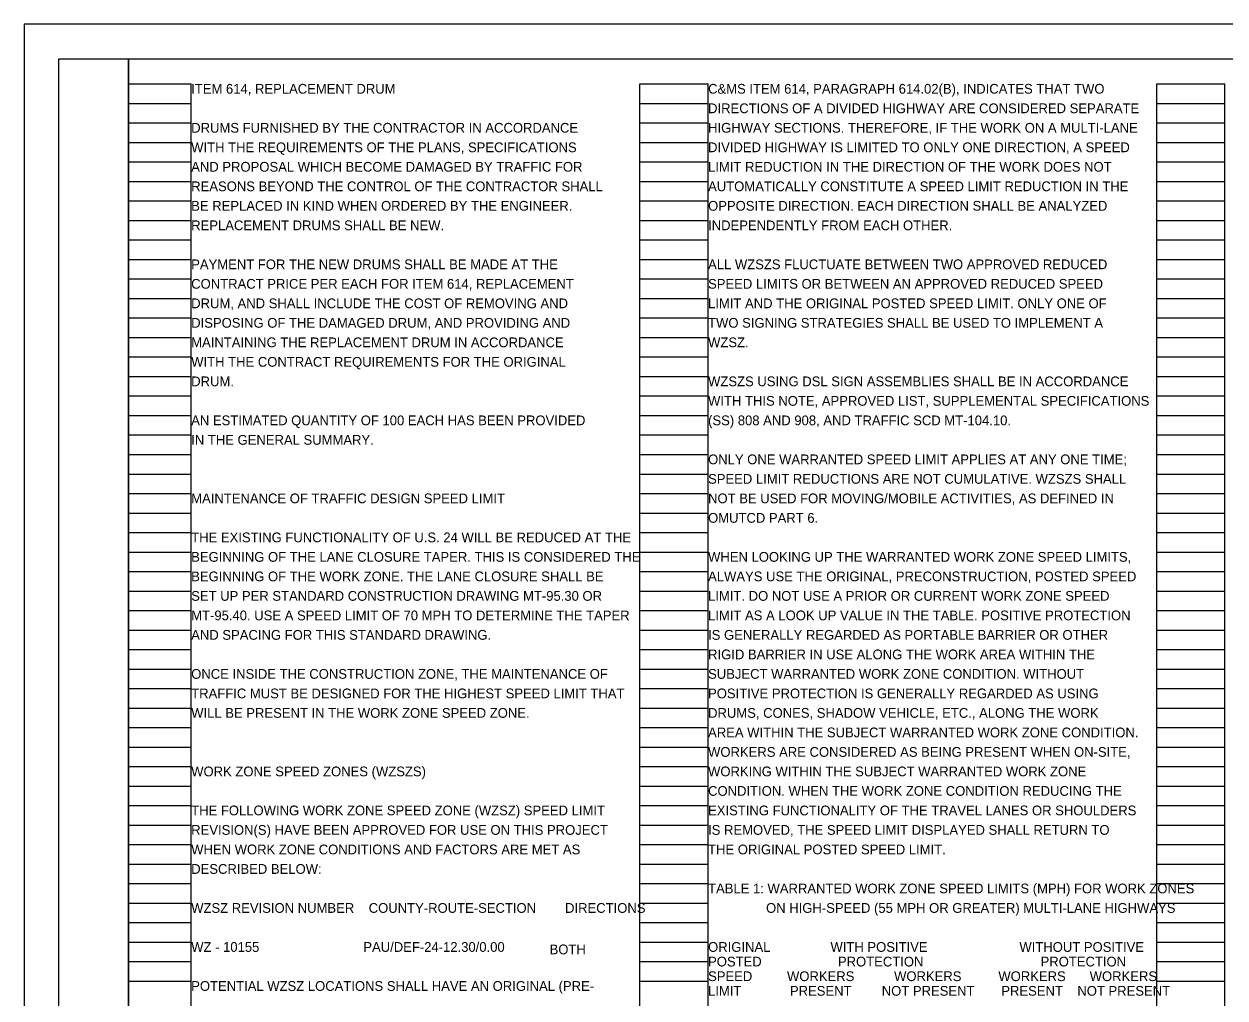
# Model space of a CAD drawing. Extents: x 0 to 34, y -6.1 to 22.
# Drawn here: x 0 to 17.24, y 8.02 to 22 of the extents above; entities that cross this region are included whole.
import ezdxf

# ---------------------------------------------------------------- set-up
doc = ezdxf.new("R2010")
doc.units = 0
for name, color, linetype in [('SH_Border', 7, 'Continuous'), ('SH_Cut_Line', 7, 'Continuous'), ('SH_Data', 7, 'Continuous'), ('SH_Text', 7, 'Continuous')]:
    doc.layers.add(name, color=color, linetype=linetype)

msp = doc.modelspace()

# ---------------------------------------------------------------- linework, layer by layer
at = {"layer": 'SH_Border'}
for points in [[(0.5, 21.5), (1.5, 21.5), (1.5, 0.5), (0.5, 0.5)], [(1.5, 21.5), (33.5, 21.5), (33.5, 0.5), (1.5, 0.5)]]:
    msp.add_lwpolyline(points, close=True, dxfattribs=at)
at = {"layer": 'SH_Cut_Line'}
msp.add_lwpolyline([(0, 0), (34, 0), (34, 22), (0, 22)], close=True, dxfattribs=at)
at = {"layer": 'SH_Data'}
for p, q in [((1.5, 0.98), (1.5, 21.14)), ((1.5, 21.14), (2.4, 21.14)), ((2.4, 0.98), (2.4, 21.14)), ((8.84, 0.98), (8.84, 21.14)), ((8.84, 21.14), (9.82, 21.14)), ((9.82, 0.98), (9.82, 21.14)), ((16.26, 0.98), (16.26, 21.14)), ((16.26, 21.14), (17.24, 21.14)), ((17.24, 0.98), (17.24, 21.14)), ((1.5, 20.86), (2.4, 20.86)), ((8.84, 20.86), (9.82, 20.86)), ((16.26, 20.86), (17.24, 20.86)), ((1.5, 20.58), (2.4, 20.58)), ((8.84, 20.58), (9.82, 20.58)), ((16.26, 20.58), (17.24, 20.58)), ((1.5, 20.3), (2.4, 20.3)), ((8.84, 20.3), (9.82, 20.3)), ((16.26, 20.3), (17.24, 20.3)), ((1.5, 20.02), (2.4, 20.02)), ((8.84, 20.02), (9.82, 20.02)), ((16.26, 20.02), (17.24, 20.02)), ((1.5, 19.74), (2.4, 19.74)), ((8.84, 19.74), (9.82, 19.74)), ((16.26, 19.74), (17.24, 19.74)), ((1.5, 19.46), (2.4, 19.46)), ((8.84, 19.46), (9.82, 19.46)), ((16.26, 19.46), (17.24, 19.46)), ((1.5, 19.18), (2.4, 19.18)), ((8.84, 19.18), (9.82, 19.18)), ((16.26, 19.18), (17.24, 19.18)), ((1.5, 18.9), (2.4, 18.9)), ((8.84, 18.9), (9.82, 18.9)), ((16.26, 18.9), (17.24, 18.9)), ((1.5, 18.62), (2.4, 18.62)), ((8.84, 18.62), (9.82, 18.62)), ((16.26, 18.62), (17.24, 18.62)), ((1.5, 18.34), (2.4, 18.34)), ((8.84, 18.34), (9.82, 18.34)), ((16.26, 18.34), (17.24, 18.34)), ((1.5, 18.06), (2.4, 18.06)), ((8.84, 18.06), (9.82, 18.06)), ((16.26, 18.06), (17.24, 18.06)), ((1.5, 17.78), (2.4, 17.78)), ((8.84, 17.78), (9.82, 17.78)), ((16.26, 17.78), (17.24, 17.78)), ((1.5, 17.5), (2.4, 17.5)), ((8.84, 17.5), (9.82, 17.5)), ((16.26, 17.5), (17.24, 17.5)), ((1.5, 17.22), (2.4, 17.22)), ((8.84, 17.22), (9.82, 17.22)), ((16.26, 17.22), (17.24, 17.22)), ((1.5, 16.94), (2.4, 16.94)), ((8.84, 16.94), (9.82, 16.94)), ((16.26, 16.94), (17.24, 16.94)), ((1.5, 16.66), (2.4, 16.66)), ((8.84, 16.66), (9.82, 16.66)), ((16.26, 16.66), (17.24, 16.66)), ((1.5, 16.38), (2.4, 16.38)), ((8.84, 16.38), (9.82, 16.38)), ((16.26, 16.38), (17.24, 16.38)), ((1.5, 16.1), (2.4, 16.1)), ((8.84, 16.1), (9.82, 16.1)), ((16.26, 16.1), (17.24, 16.1)), ((1.5, 15.82), (2.4, 15.82)), ((8.84, 15.82), (9.82, 15.82)), ((16.26, 15.82), (17.24, 15.82)), ((1.5, 15.54), (2.4, 15.54)), ((8.84, 15.54), (9.82, 15.54)), ((16.26, 15.54), (17.24, 15.54)), ((1.5, 15.26), (2.4, 15.26)), ((8.84, 15.26), (9.82, 15.26)), ((16.26, 15.26), (17.24, 15.26)), ((1.5, 14.98), (2.4, 14.98)), ((8.84, 14.98), (9.82, 14.98)), ((16.26, 14.98), (17.24, 14.98)), ((1.5, 14.7), (2.4, 14.7)), ((8.84, 14.7), (9.82, 14.7)), ((16.26, 14.7), (17.24, 14.7)), ((1.5, 14.42), (2.4, 14.42)), ((8.84, 14.42), (9.82, 14.42)), ((16.26, 14.42), (17.24, 14.42)), ((1.5, 14.14), (2.4, 14.14)), ((8.84, 14.14), (9.82, 14.14)), ((16.26, 14.14), (17.24, 14.14)), ((1.5, 13.86), (2.4, 13.86)), ((8.84, 13.86), (9.82, 13.86)), ((16.26, 13.86), (17.24, 13.86)), ((1.5, 13.58), (2.4, 13.58)), ((8.84, 13.58), (9.82, 13.58)), ((16.26, 13.58), (17.24, 13.58)), ((1.5, 13.3), (2.4, 13.3)), ((8.84, 13.3), (9.82, 13.3)), ((16.26, 13.3), (17.24, 13.3)), ((1.5, 13.02), (2.4, 13.02)), ((8.84, 13.02), (9.82, 13.02)), ((16.26, 13.02), (17.24, 13.02)), ((1.5, 12.74), (2.4, 12.74)), ((8.84, 12.74), (9.82, 12.74)), ((16.26, 12.74), (17.24, 12.74)), ((1.5, 12.46), (2.4, 12.46)), ((8.84, 12.46), (9.82, 12.46)), ((16.26, 12.46), (17.24, 12.46)), ((1.5, 12.18), (2.4, 12.18)), ((8.84, 12.18), (9.82, 12.18)), ((16.26, 12.18), (17.24, 12.18)), ((1.5, 11.9), (2.4, 11.9)), ((8.84, 11.9), (9.82, 11.9)), ((16.26, 11.9), (17.24, 11.9)), ((1.5, 11.62), (2.4, 11.62)), ((8.84, 11.62), (9.82, 11.62)), ((16.26, 11.62), (17.24, 11.62)), ((1.5, 11.34), (2.4, 11.34)), ((8.84, 11.34), (9.82, 11.34)), ((16.26, 11.34), (17.24, 11.34)), ((1.5, 11.06), (2.4, 11.06)), ((8.84, 11.06), (9.82, 11.06)), ((16.26, 11.06), (17.24, 11.06)), ((1.5, 10.78), (2.4, 10.78)), ((8.84, 10.78), (9.82, 10.78)), ((16.26, 10.78), (17.24, 10.78)), ((1.5, 10.5), (2.4, 10.5)), ((8.84, 10.5), (9.82, 10.5)), ((16.26, 10.5), (17.24, 10.5)), ((1.5, 10.22), (2.4, 10.22)), ((8.84, 10.22), (9.82, 10.22)), ((16.26, 10.22), (17.24, 10.22)), ((1.5, 9.94), (2.4, 9.94)), ((8.84, 9.94), (9.82, 9.94)), ((16.26, 9.94), (17.24, 9.94)), ((1.5, 9.66), (2.4, 9.66)), ((8.84, 9.66), (9.82, 9.66)), ((16.26, 9.66), (17.24, 9.66)), ((1.5, 9.38), (2.4, 9.38)), ((8.84, 9.38), (9.82, 9.38)), ((16.26, 9.38), (17.24, 9.38)), ((1.5, 9.1), (2.4, 9.1)), ((8.84, 9.1), (9.82, 9.1)), ((16.26, 9.1), (17.24, 9.1)), ((1.5, 8.82), (2.4, 8.82)), ((8.84, 8.82), (9.82, 8.82)), ((16.26, 8.82), (17.24, 8.82)), ((1.5, 8.54), (2.4, 8.54)), ((8.84, 8.54), (9.82, 8.54)), ((16.26, 8.54), (17.24, 8.54)), ((1.5, 8.26), (2.4, 8.26)), ((8.84, 8.26), (9.82, 8.26)), ((16.26, 8.26), (17.24, 8.26))]:
    msp.add_line(p, q, dxfattribs=at)

# ---------------------------------------------------------------- texts
at = {"layer": 'SH_Text'}
for s, p in [('ITEM 614, REPLACEMENT DRUM', (2.4, 21)), ('C&MS ITEM 614, PARAGRAPH 614.02(B), INDICATES THAT TWO', (9.82, 21)), ('DIRECTIONS OF A DIVIDED HIGHWAY ARE CONSIDERED SEPARATE', (9.82, 20.72)), ('DRUMS FURNISHED BY THE CONTRACTOR IN ACCORDANCE', (2.4, 20.44)), ('HIGHWAY SECTIONS. THEREFORE, IF THE WORK ON A MULTI-LANE', (9.82, 20.44)), ('WITH THE REQUIREMENTS OF THE PLANS, SPECIFICATIONS', (2.4, 20.16)), ('DIVIDED HIGHWAY IS LIMITED TO ONLY ONE DIRECTION, A SPEED', (9.82, 20.16)), ('AND PROPOSAL WHICH BECOME DAMAGED BY TRAFFIC FOR', (2.4, 19.88)), ('LIMIT REDUCTION IN THE DIRECTION OF THE WORK DOES NOT', (9.82, 19.88)), ('REASONS BEYOND THE CONTROL OF THE CONTRACTOR SHALL', (2.4, 19.6)), ('AUTOMATICALLY CONSTITUTE A SPEED LIMIT REDUCTION IN THE', (9.82, 19.6)), ('BE REPLACED IN KIND WHEN ORDERED BY THE ENGINEER.', (2.4, 19.32)), ('OPPOSITE DIRECTION. EACH DIRECTION SHALL BE ANALYZED', (9.82, 19.32)), ('REPLACEMENT DRUMS SHALL BE NEW.', (2.4, 19.04)), ('INDEPENDENTLY FROM EACH OTHER.', (9.82, 19.04)), ('PAYMENT FOR THE NEW DRUMS SHALL BE MADE AT THE', (2.4, 18.48)), ('ALL WZSZS FLUCTUATE BETWEEN TWO APPROVED REDUCED', (9.82, 18.48)), ('CONTRACT PRICE PER EACH FOR ITEM 614, REPLACEMENT', (2.4, 18.2)), ('SPEED LIMITS OR BETWEEN AN APPROVED REDUCED SPEED', (9.82, 18.2)), ('DRUM, AND SHALL INCLUDE THE COST OF REMOVING AND', (2.4, 17.92)), ('LIMIT AND THE ORIGINAL POSTED SPEED LIMIT. ONLY ONE OF', (9.82, 17.92)), ('DISPOSING OF THE DAMAGED DRUM, AND PROVIDING AND', (2.4, 17.64)), ('TWO SIGNING STRATEGIES SHALL BE USED TO IMPLEMENT A', (9.82, 17.64)), ('MAINTAINING THE REPLACEMENT DRUM IN ACCORDANCE', (2.4, 17.36)), ('WZSZ.', (9.82, 17.36)), ('WITH THE CONTRACT REQUIREMENTS FOR THE ORIGINAL', (2.4, 17.08)), ('DRUM.', (2.4, 16.8)), ('WZSZS USING DSL SIGN ASSEMBLIES SHALL BE IN ACCORDANCE', (9.82, 16.8)), ('WITH THIS NOTE, APPROVED LIST, SUPPLEMENTAL SPECIFICATIONS', (9.82, 16.52)), ('AN ESTIMATED QUANTITY OF 100 EACH HAS BEEN PROVIDED', (2.4, 16.24)), ('(SS) 808 AND 908, AND TRAFFIC SCD MT-104.10.', (9.82, 16.24)), ('IN THE GENERAL SUMMARY.', (2.4, 15.96)), ('ONLY ONE WARRANTED SPEED LIMIT APPLIES AT ANY ONE TIME;', (9.82, 15.68)), ('SPEED LIMIT REDUCTIONS ARE NOT CUMULATIVE. WZSZS SHALL', (9.82, 15.4)), ('MAINTENANCE OF TRAFFIC DESIGN SPEED LIMIT', (2.4, 15.12)), ('NOT BE USED FOR MOVING/MOBILE ACTIVITIES, AS DEFINED IN', (9.82, 15.12)), ('OMUTCD PART 6.', (9.82, 14.84)), ('THE EXISTING FUNCTIONALITY OF U.S. 24 WILL BE REDUCED AT THE', (2.4, 14.56)), ('BEGINNING OF THE LANE CLOSURE TAPER. THIS IS CONSIDERED THE', (2.4, 14.28)), ('WHEN LOOKING UP THE WARRANTED WORK ZONE SPEED LIMITS,', (9.82, 14.28)), ('BEGINNING OF THE WORK ZONE. THE LANE CLOSURE SHALL BE', (2.4, 14)), ('ALWAYS USE THE ORIGINAL, PRECONSTRUCTION, POSTED SPEED', (9.82, 14)), ('SET UP PER STANDARD CONSTRUCTION DRAWING MT-95.30 OR ', (2.4, 13.72)), ('LIMIT. DO NOT USE A PRIOR OR CURRENT WORK ZONE SPEED', (9.82, 13.72)), ('MT-95.40. USE A SPEED LIMIT OF 70 MPH TO DETERMINE THE TAPER ', (2.4, 13.44)), ('LIMIT AS A LOOK UP VALUE IN THE TABLE. POSITIVE PROTECTION', (9.82, 13.44)), ('AND SPACING FOR THIS STANDARD DRAWING.', (2.4, 13.16)), ('IS GENERALLY REGARDED AS PORTABLE BARRIER OR OTHER', (9.82, 13.16)), ('RIGID BARRIER IN USE ALONG THE WORK AREA WITHIN THE', (9.82, 12.88)), ('ONCE INSIDE THE CONSTRUCTION ZONE, THE MAINTENANCE OF', (2.4, 12.6)), ('SUBJECT WARRANTED WORK ZONE CONDITION. WITHOUT', (9.82, 12.6)), ('TRAFFIC MUST BE DESIGNED FOR THE HIGHEST SPEED LIMIT THAT', (2.4, 12.32)), ('POSITIVE PROTECTION IS GENERALLY REGARDED AS USING', (9.82, 12.32)), ('WILL BE PRESENT IN THE WORK ZONE SPEED ZONE. ', (2.4, 12.04)), ('DRUMS, CONES, SHADOW VEHICLE, ETC., ALONG THE WORK', (9.82, 12.04)), ('AREA WITHIN THE SUBJECT WARRANTED WORK ZONE CONDITION.', (9.82, 11.76)), ('WORKERS ARE CONSIDERED AS BEING PRESENT WHEN ON-SITE,', (9.82, 11.48)), ('WORK ZONE SPEED ZONES (WZSZS)', (2.4, 11.2)), ('WORKING WITHIN THE SUBJECT WARRANTED WORK ZONE', (9.82, 11.2)), ('CONDITION. WHEN THE WORK ZONE CONDITION REDUCING THE', (9.82, 10.92)), ('THE FOLLOWING WORK ZONE SPEED ZONE (WZSZ) SPEED LIMIT', (2.4, 10.64)), ('EXISTING FUNCTIONALITY OF THE TRAVEL LANES OR SHOULDERS', (9.82, 10.64)), ('REVISION(S) HAVE BEEN APPROVED FOR USE ON THIS PROJECT', (2.4, 10.36)), ('IS REMOVED, THE SPEED LIMIT DISPLAYED SHALL RETURN TO', (9.82, 10.36)), ('WHEN WORK ZONE CONDITIONS AND FACTORS ARE MET AS', (2.4, 10.08)), ('THE ORIGINAL POSTED SPEED LIMIT.', (9.82, 10.08)), ('DESCRIBED BELOW:', (2.4, 9.8)), ('TABLE 1: WARRANTED WORK ZONE SPEED LIMITS (MPH) FOR WORK ZONES', (9.82, 9.52)), ('WZSZ REVISION NUMBER    COUNTY-ROUTE-SECTION        DIRECTIONS', (2.4, 9.24)), ('                ON HIGH-SPEED (55 MPH OR GREATER) MULTI-LANE HIGHWAYS', (9.82, 9.24)), ('WZ - 10155', (2.4, 8.68)), ('PAU/DEF-24-12.30/0.00', (4.871, 8.68)), ('ORIGINAL ', (9.82, 8.68)), ('WITH POSITIVE ', (11.577, 8.68)), ('WITHOUT POSITIVE ', (14.289, 8.68)), ('BOTH', (7.545, 8.645)), ('POSTED ', (9.82, 8.47)), ('PROTECTION', (11.684, 8.47)), ('PROTECTION', (14.593, 8.47)), ('SPEED ', (9.82, 8.26)), ('WORKERS', (10.953, 8.26)), ('WORKERS', (12.49, 8.26)), ('WORKERS', (13.987, 8.26)), ('WORKERS', (15.298, 8.26)), ('POTENTIAL WZSZ LOCATIONS SHALL HAVE AN ORIGINAL (PRE-', (2.4, 8.12)), ('LIMIT', (9.82, 8.05)), ('PRESENT', (10.995, 8.05)), ('NOT PRESENT', (12.313, 8.05)), ('PRESENT', (14.029, 8.05)), ('NOT PRESENT', (15.121, 8.05))]:
    msp.add_text(s, height=0.14, dxfattribs=at).set_placement(p)

doc.saveas('drawing.dxf')
